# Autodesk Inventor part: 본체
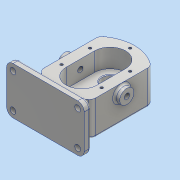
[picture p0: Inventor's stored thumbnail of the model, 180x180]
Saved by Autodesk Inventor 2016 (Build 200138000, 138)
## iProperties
Created: 2019-03
Part Number: 본체
Material: 알루미늄 6061
Document SubType Name: Modeling
Designer: 3sil_cad0123
Density: 2.7 g/cm^3
Appearance: 알루미늄 - 평지
Mass: 1186.44 g
Surface Area: 720.896 cm^2
Volume: 439.422 cm^3
Author: 3sil_cad0123
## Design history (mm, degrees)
sketch "스케치1"
  geometry: L1 (-40, 60)-(40, 60); L2 (40, 60)-(40, 0); L3 (40, 0)-(-40, 0); L4 (-40, 0)-(-40, 60); L5 (0, 60)-(0, 0); A1 r 60 centre (0, 0) between (40, 44.721) and (-40, 44.721); 1 further point
  constraints: 10 end point, 2 coincident, 2 midpoint, 2 parallel, 2 point on circle, 2 point on line, 1 centre point, 1 horizontal, 1 perpendicular
  dimensions: "d0" = 80 distance of L1.start L1.end; "d1" = 60 distance of L3.end L1.start; "d2" = 120 diameter of A1
extrude "돌출1" new body sketch "스케치1" stored distance "d3" = 53; taper "d4" = 0 deg
sketch "스케치2"
  geometry: L1 (-24, -22)-(24, -22); L2 (24, -22)-(24, 22); L3 (24, 22)-(-24, 22); L4 (-24, 22)-(-24, -22); L5 (-24, -22)-(24, 22); L6 (24, -22)-(-24, 22); C1 r 24 at (0, 22); C2 r 24 at (0, -22); A1 r 60 centre (0, 0) between (40, 44.721) and (-40, 44.721) reference; A2 r 60 centre (0, 0) between (-40, -44.721) and (40, -44.721) reference; 1 further point
  constraints: 12 end point, 4 midpoint, 2 centre point, 2 parallel, 1 coincident, 1 horizontal, 1 perpendicular
  dimensions: "d5" = 48 diameter of C1; "d6" = 48 distance of L2.end L3.end; "d7" = 22 vertical distance of A1.centre L2.end; "d8" = 48 diameter of C2
extrude "돌출2" cut sketch "스케치2" distance "d9" = 29; taper "d10" = 0 deg
sketch "스케치3"
  geometry: L1 (0, 0)-(0, -89.443) reference; C1 r 11 at (14, -44.721); 1 further point
  constraints: 1 centre point, 1 horizontal alignment
  dimensions: "d11" = 22 diameter of C1; "d12" = 14 distance from line of L1 C1.centre
extrude "돌출3" join sketch "스케치3" distance "d13" = 8; taper "d14" = 0 deg
sketch "스케치4"
  geometry: L1 (53, 0)-(53, -89.443) reference; C1 r 11 at (39, -44.721); 1 further point
  constraints: 1 centre point, 1 horizontal alignment
  dimensions: "d15" = 22 diameter of C1; "d16" = 14 distance from line of L1 C1.centre
extrude "돌출4" join sketch "스케치4" distance "d17" = 8; taper "d18" = 0 deg
sketch "스케치5"
  geometry: C1 r 11 at (0, 0) reference; 1 further point
hole "구멍1" sketch "스케치5" at (0, 0) diameter "d19" = 8.376; stored, may be unused: countersink angle "d23" = 90 deg, drill point angle "d25" = 0 deg; dims "d20" = 100, "d21" = 4, "d22" = 2, "d24" = 27.3
sketch "스케치6"
  geometry: C1 r 12.5 at (0, 22); C2 r 12.5 at (0, -22); A1 r 24 centre (0, 22) between (24, 22) and (-24, 22) reference; A2 r 24 centre (0, -22) between (-24, -22) and (24, -22) reference; 1 further point
  constraints: 2 centre point, 2 coincident
  dimensions: "d26" = 25 diameter of C1; "d27" = 25 diameter of C2
extrude "돌출5" cut sketch "스케치6" distance "d28" = 15; taper "d29" = 0 deg
sketch "스케치9"
  geometry: L1 (-31, -22)-(31, -22); L2 (31, -22)-(31, 22); L3 (31, 22)-(-31, 22); L4 (-31, 22)-(-31, -22); L5 (-31, -22)-(31, 22); L6 (31, -22)-(-31, 22); A1 r 24 centre (0, 22) between (24, 22) and (-24, 22) reference; A2 r 24 centre (0, -22) between (-24, -22) and (24, -22) reference; A3 r 60 centre (0, 0) between (-40, -44.721) and (40, -44.721) reference; A4 r 31 centre (0, 22) between (0, 53) and (-31, 22); A5 r 31 centre (0, -22) between (0, -53) and (31, -22); 2 further points
  constraints: 12 end point, 4 coincident, 4 point on circle, 2 centre point, 2 midpoint, 2 parallel, 1 horizontal, 1 perpendicular, 1 point on line
  dimensions: "d39" = 44 distance of L1.end L2.end; "d40" = 62 distance of L2.end L3.end; "d41" = 62 diameter of A4; "d42" = 62 diameter of A5
hole "구멍2" sketch "스케치9" at (0, 53), (-31, 22), (-31, -22), (0, -53), (31, -22), (31, 22) diameter "d43" = 4.134; stored, may be unused: countersink angle "d47" = 90 deg, drill point angle "d49" = 118 deg; dims "d44" = 10, "d45" = 4, "d46" = 2, "d48" = 12
sketch "스케치11"
  geometry: L1 (-60, -78)-(60, -78); L2 (60, -78)-(60, -68); L3 (60, -68)-(-60, -68); L4 (-60, -68)-(-60, -78); L5 (-60, -78)-(60, -68); L6 (60, -78)-(-60, -68); A1 r 60 centre (0, 0) between (40, 44.721) and (-40, 44.721) reference; 2 further points
  constraints: 12 end point, 3 midpoint, 2 parallel, 1 horizontal, 1 perpendicular, 1 vertical alignment
  dimensions: "d53" = 10 distance of L1.end L2.end; "d54" = 120 distance of L1.start L1.end; "d55" = 78 distance from line of A1.centre L1
extrude "돌출9" join sketch "스케치11" distance "d56" = 73; taper "d57" = 0 deg
sketch "스케치12"
  geometry: L1 (0, 0)-(120, 0) reference; L2 (54, -43)-(66, -43); L3 (66, -43)-(66, 0); L4 (66, 0)-(54, 0); L5 (54, 0)-(54, -43); L6 (54, -43)-(66, 0); L7 (66, -43)-(54, 0); 3 further points
  constraints: 12 end point, 3 midpoint, 2 parallel, 1 horizontal, 1 perpendicular, 1 point on line, 1 vertical alignment
  dimensions: "d58" = 12 distance of L2.start L2.end; "d59" = 43 distance of L2.end L3.end
extrude "돌출10" join sketch "스케치12" stored distance "d60" = 73; taper "d61" = 0 deg
fillet "모깎기1" dims "d62" = 10
sketch "스케치13"
  geometry: A1 r 10 centre (56, -20) between (56, -30) and (66, -20) reference; A2 r 10 centre (56, 33) between (66, 33) and (56, 43) reference; A3 r 10 centre (-44, 33) between (-44, 43) and (-54, 33) reference; A4 r 10 centre (-44, -20) between (-54, -20) and (-44, -30) reference; 1 further point
hole "구멍3" sketch "스케치13" at (-44, 33), (-44, -20), (56, -20), (56, 33) diameter "d63" = 9; stored, may be unused: countersink angle "d67" = 90 deg, drill point angle "d69" = 0 deg; dims "d64" = 10, "d65" = 4, "d66" = 2, "d68" = 12
sketch "스케치14"
  geometry: C1 r 12.5 at (0, 22) reference; C2 r 19 at (0, 22)
  constraints: 1 centre point, 1 coincident
  dimensions: "d76" = 38 diameter of C2
extrude "돌출11" join sketch "스케치14" distance "d77" = 17; taper "d78" = 0 deg
sketch "스케치15"
  geometry: C1 r 12.5 at (0, 0) reference; C2 r 8.5 at (0, 0); 1 further point
  constraints: 1 centre point, 1 coincident
  dimensions: "d79" = 17 diameter of C2
extrude "돌출12" cut sketch "스케치15" stored distance "d80" = 17; taper "d81" = 0 deg
sketch "스케치16"
  geometry: C1 r 19 at (0, 0) reference; C2 r 14 at (0, 0); 1 further point
  constraints: 1 centre point, 1 coincident
  dimensions: "d82" = 28 diameter of C2
extrude "돌출13" cut sketch "스케치16" distance "d83" = 7.3; taper "d84" = 0 deg
chamfer "모따기3" distance "d85" = 0.7; stored, may be unused: second distance "d86" = 2, angle "d87" = 30 deg
fillet "모깎기2" dims "d88" = 0.5
fillet "모깎기3" dims "d89" = 3
fillet "모깎기4" dims "d90" = 10
chamfer "모따기4" distance "d91" = 1; stored, may be unused: second distance "d92" = 2, angle "d93" = 30 deg
node "작업 평면1"
sketch "스케치17"
  geometry: L1 (0, -3)-(100, -3) reference; L2 (-10, 60)-(-10, 7) reference; 2 further points
  constraints: 1 other
  dimensions: "d95" = 10 distance from line of L1 point (50, 7); "d96" = 60 distance from line of L2 point (50, 7)
feature "엠보싱1" sketch "스케치17" dims "d0" = 80, "d1" = 60, "d2" = 120, "d5" = 48, "d6" = 48, "d7" = 22, "d8" = 48, "d97" = 0.5, "d98" = 0
fillet "모깎기5" dims "d99" = 3
node "솔리드1"
mirror "대칭1"
other parameters: "d94" = 51.75
